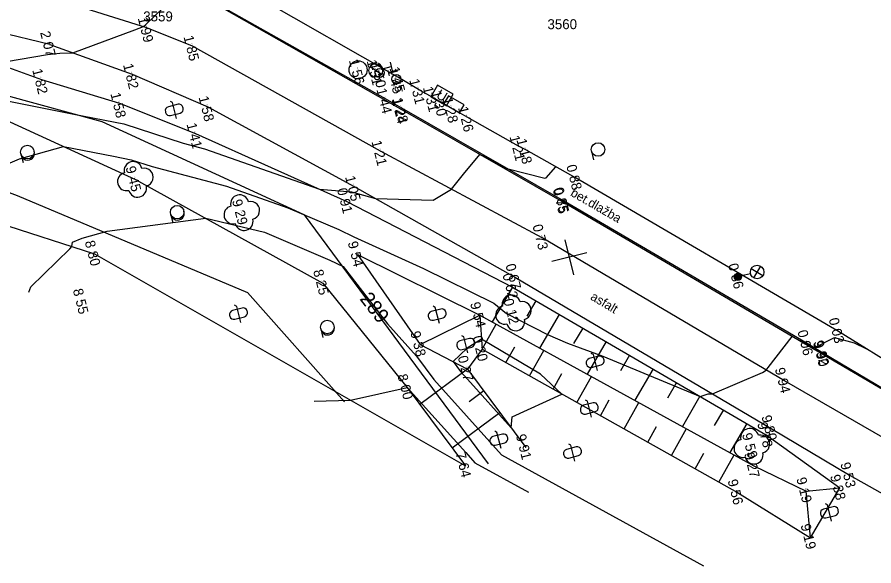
# Model space of a CAD drawing. Extents: x -740053 to -737517, y -1033516 to -1032488.
# Drawn here: x -739094.08 to -739046.71, y -1032604 to -1032573.66 of the extents above; entities that cross this region are included whole.
import ezdxf

# ---------------------------------------------------------------- set-up
doc = ezdxf.new("R2010")
doc.units = 0
for name, color, linetype in [('bod-cislo', 7, 'Continuous'), ('bod-oznac', 7, 'Continuous'), ('bod-vyska', 7, 'Continuous'), ('bod-vyska100', 7, 'Continuous'), ('chodnik', 7, 'Continuous'), ('Contours', 7, 'Continuous'), ('Contours highlighted', 7, 'Continuous'), ('Contours text', 7, 'Continuous'), ('ctv-sit', 7, 'Continuous'), ('el-zariz', 7, 'Continuous'), ('Hranice-zelene', 7, 'Continuous'), ('nazvy-bud-povr', 7, 'Continuous'), ('objekty-na-kanalizaci', 7, 'Continuous'), ('objekty-na-plynovodu', 7, 'Continuous'), ('objekty-na-vodovodu', 7, 'Continuous'), ('osa-komunikace', 7, 'Continuous'), ('Ploty-Vjezd', 7, 'Continuous'), ('podezdivka', 7, 'Continuous'), ('silnice', 7, 'Continuous'), ('Technické šrafy', 7, 'Continuous'), ('Terenni-hrana', 7, 'Continuous'), ('Znacky-kultury', 7, 'Continuous')]:
    doc.layers.add(name, color=color, linetype=linetype)

# ---------------------------------------------------------------- blocks, each defined once
blk = doc.blocks.new('el_lamst')
for p, q in [((-0.53, 1.658), (0.53, 2.719)), ((-0.53, 2.719), (0.53, 1.658)), ((0, 1.439), (0, 0.4))]:
    blk.add_line(p, q)
for centre, radius in [((0, 2.189), 0.75), ((0, 0), 0.4), ((0, 0), 0.351), ((0, 0), 0.305), ((0, 0), 0.305), ((0, 0), 0.26), ((0, 0), 0.206), ((0, 0), 0.161), ((0, 0), 0.115), ((0, 0), 0.0619)]:
    blk.add_circle(centre, radius)
blk = doc.blocks.new('el_rozd')
for p, q in [((-1.001, 1.001), (-1.001, 0)), ((1.001, 1.001), (-1.001, 1.001)), ((1.001, 0), (1.001, 1.001)), ((-1.001, 0), (1.001, 0))]:
    blk.add_line(p, q)
blk = doc.blocks.new('po_sasou')
for p, q in [((-1.055, 0.76), (-1.055, -0.734)), ((0.948, 0.76), (-1.055, 0.76)), ((0.948, -0.734), (0.948, 0.76)), ((-1.055, -0.734), (0.948, -0.734))]:
    blk.add_line(p, q)
blk.add_text('U', height=1.095).set_placement((-0.583, -0.534))
blk = doc.blocks.new('vo_soupe')
blk.add_circle((0, 0), 0.5)
blk = doc.blocks.new('po_hydpo')
for p, q in [((-0.5, 1.756), (0.5, 1.756)), ((0, 0.75), (0, 1.756)), ((-0.562, -0.496), (0.562, 0.496))]:
    blk.add_line(p, q)
blk.add_circle((0, 0), 0.75)
blk = doc.blocks.new('po_kansa')
blk.add_circle((0, 0), 1)
blk = doc.blocks.new('POINT_DISPLAY')
blk.add_line((0, 0), (0, 0))
blk = doc.blocks.new('p_strom')
for centre, start, end in [((0, 1), 0, 180), ((-1, 0), 90, 270), ((1, 0), 270, 90), ((0, -1), 180, 0)]:
    blk.add_arc(centre, 1, start, end)
at = {"rotation": -180}
blk.add_blockref('POINT_DISPLAY', (0, 0), dxfattribs=at)
blk = doc.blocks.new('p_leskro')
blk.add_line((0, -0.75), (1.001, -0.75))
blk.add_circle((0, 0), 0.75)
blk.add_arc((0.134, 0), 0.75, 264.88323, 95.11677)
blk = doc.blocks.new('p_neplod')
for p, q in [((0.052, 1.005), (-0.044, 1.005)), ((-0.824, 0.004), (-0.994, -0.184)), ((1.002, 0.004), (-0.824, 0.004)), ((-0.494, 0.555), (-0.494, -0.548)), ((0.502, -0.548), (0.502, 0.555)), ((-0.044, -0.998), (0.052, -0.998))]:
    blk.add_line(p, q)
for centre, start, end in [((-0.044, 0.555), 90, 180), ((0.052, 0.555), 0, 90), ((-0.044, -0.548), 180, 270), ((0.052, -0.548), 270, 0)]:
    blk.add_arc(centre, 0.45, start, end)
blk = doc.blocks.new('p_zahr')
blk.add_line((0, -0.75), (0.993, -0.75))
blk.add_circle((0, 0), 0.75)
blk = doc.blocks.new('ctvsit')
for p, q in [((0, -2), (0, 2)), ((2, 0), (-2, 0))]:
    blk.add_line(p, q)

msp = doc.modelspace()

# ---------------------------------------------------------------- linework, layer by layer
at = {"layer": 'chodnik'}
for p, q in [((-739073.709, -1032578.179), (-739083.274, -1032572.791)), ((-739072.816, -1032578.697), (-739073.709, -1032578.179)), ((-739063.875, -1032583.819), (-739072.816, -1032578.697)), ((-739063.171, -1032582.559), (-739065.956, -1032581.002)), ((-739050.391, -1032591.706), (-739063.875, -1032583.819)), ((-739049.498, -1032592.265), (-739050.391, -1032591.706)), ((-739042.865, -1032596.205), (-739049.498, -1032592.265))]:
    msp.add_line(p, q, dxfattribs=at)
at = {"layer": 'Contours'}
for points in [[(-739113.301, -1032585.141), (-739112.468, -1032582.989), (-739111.701, -1032582.242), (-739110.056, -1032580.212), (-739109.326, -1032576.302), (-739107.888, -1032575.694), (-739099.85, -1032575.084), (-739095.564, -1032576.081), (-739094.668, -1032576.103), (-739092.396, -1032575.717), (-739091.714, -1032575.641), (-739090.99, -1032575.637), (-739087.57, -1032574.358), (-739087.088, -1032574.182), (-739086.97, -1032574.064), (-739086.008, -1032573.134), (-739085.07, -1032572.23), (-739084.95, -1032572.102), (-739084.144, -1032572.423), (-739083.274, -1032572.791), (-739082.501, -1032571.634), (-739082.49, -1032571.595), (-739082.473, -1032571.58)], [(-739106.678, -1032586.38), (-739106.087, -1032584.852), (-739104.854, -1032583.652), (-739103.724, -1032582.257), (-739103.221, -1032579.569), (-739099.261, -1032577.893), (-739097.133, -1032577.731), (-739095.113, -1032578.202), (-739090.94, -1032579.015), (-739088.178, -1032579.564), (-739084.905, -1032580.63), (-739083.714, -1032580.945), (-739077.353, -1032583.178), (-739075.586, -1032583.317), (-739074.268, -1032583.681), (-739071.085, -1032583.783), (-739070.071, -1032583.165), (-739069.392, -1032582.342), (-739068.487, -1032581.25), (-739068.119, -1032581.426), (-739066.994, -1032582.032), (-739064.906, -1032582.558), (-739064.821, -1032582.539), (-739064.285, -1032581.936)], [(-739093.433, -1032588.859), (-739093.324, -1032588.578), (-739091.162, -1032586.473), (-739091.059, -1032586.346), (-739091.013, -1032586.102), (-739090.484, -1032585.878), (-739089.1, -1032585.486), (-739083.651, -1032584.78), (-739080.403, -1032585.555), (-739076.796, -1032587.091), (-739076.056, -1032587.446), (-739073.604, -1032590.613), (-739071.993, -1032592.41), (-739071.038, -1032593.692), (-739069.231, -1032595.703), (-739067.296, -1032597.857), (-739056.121, -1032604.001)], [(-739077.664, -1032594.886), (-739075.655, -1032594.831), (-739072.507, -1032594.139), (-739069.277, -1032597.734), (-739068.765, -1032598.304), (-739065.807, -1032599.931)]]:
    msp.add_lwpolyline(points, dxfattribs=at)
at = {"layer": 'Contours highlighted'}
for points in [[(-739097.117, -1032582.835), (-739093.942, -1032581.492), (-739091.522, -1032580.807), (-739088.747, -1032581.348), (-739087.767, -1032581.543), (-739086.606, -1032581.921), (-739082.509, -1032583.006), (-739079.11, -1032584.199), (-739076.3, -1032585.396), (-739075.454, -1032585.802), (-739071.61, -1032587.552), (-739067.726, -1032589.481), (-739067.02, -1032590.039), (-739064.76, -1032591.204), (-739063.653, -1032591.681), (-739061.69, -1032592.401), (-739056.306, -1032594.636), (-739055.876, -1032594.497), (-739055.637, -1032594.486), (-739052.868, -1032593.305), (-739052.662, -1032593.174), (-739052.554, -1032593.04), (-739051.232, -1032591.313), (-739050.072, -1032591.931), (-739050.009, -1032591.946), (-739048.891, -1032591.37), (-739047.791, -1032591.659), (-739047.111, -1032592.004)], [(-739066.707, -1032595.767), (-739063.958, -1032594.501), (-739065.136, -1032593.408), (-739068.405, -1032591.456), (-739069.204, -1032591.958), (-739069.97, -1032592.708), (-739069.57, -1032593.245), (-739069.186, -1032593.673), (-739066.763, -1032596.369), (-739066.707, -1032595.767)]]:
    msp.add_lwpolyline(points, dxfattribs=at)
at = {"layer": 'Hranice-zelene'}
for points in [[(-739078.209, -1032584.588), (-739089.378, -1032579.455), (-739100.31, -1032576.455), (-739110.269, -1032573.521), (-739112.226, -1032576.709), (-739094.074, -1032583.522), (-739081.338, -1032588.881), (-739075.972, -1032594.939)], [(-739078.209, -1032584.588), (-739068.034, -1032598.36)]]:
    msp.add_lwpolyline(points, dxfattribs=at)
at = {"layer": 'osa-komunikace'}
for p, q in [((-739086.9, -1032574.24), (-739091.787, -1032572.728)), ((-739084.373, -1032575.265), (-739086.9, -1032574.24)), ((-739073.983, -1032581.064), (-739084.373, -1032575.265)), ((-739065.041, -1032585.866), (-739073.983, -1032581.064)), ((-739051.644, -1032593.775), (-739065.041, -1032585.866)), ((-739044.094, -1032598.123), (-739051.644, -1032593.775))]:
    msp.add_line(p, q, dxfattribs=at)
at = {"layer": 'Ploty-Vjezd'}
for p, q in [((-739071.136, -1032578.078), (-739071.891, -1032577.66)), ((-739066.349, -1032580.792), (-739069.196, -1032579.188))]:
    msp.add_line(p, q, dxfattribs=at)
msp.add_lwpolyline([(-739044.07, -1032593.837), (-739045.041, -1032593.298), (-739048.663, -1032591.034)], dxfattribs=at)
at = {"layer": 'podezdivka'}
for p, q in [((-739072.986, -1032576.997), (-739083.163, -1032571.186)), ((-739071.891, -1032577.66), (-739072.986, -1032576.997)), ((-739069.196, -1032579.188), (-739071.136, -1032578.078)), ((-739065.956, -1032581.002), (-739066.349, -1032580.792)), ((-739048.663, -1032591.034), (-739063.171, -1032582.559))]:
    msp.add_line(p, q, dxfattribs=at)
at = {"layer": 'silnice'}
for p, q in [((-739072.867, -1032578.741), (-739083.293, -1032572.838)), ((-739092.263, -1032575.178), (-739100.244, -1032573.217)), ((-739092.263, -1032575.178), (-739087.716, -1032576.817)), ((-739087.716, -1032576.817), (-739083.541, -1032578.613)), ((-739083.541, -1032578.613), (-739075.44, -1032583.018)), ((-739063.926, -1032583.863), (-739072.867, -1032578.741)), ((-739075.44, -1032583.018), (-739066.531, -1032588.056)), ((-739049.539, -1032592.306), (-739063.926, -1032583.863)), ((-739066.531, -1032588.056), (-739052.385, -1032596.405)), ((-739042.882, -1032596.22), (-739049.539, -1032592.306)), ((-739052.385, -1032596.405), (-739048.027, -1032599.01)), ((-739048.027, -1032599.01), (-739045.626, -1032600.354))]:
    msp.add_line(p, q, dxfattribs=at)
at = {"layer": 'Technické šrafy'}
for p, q in [((-739066.697, -1032588.582), (-739067.822, -1032590.513)), ((-739065.401, -1032589.337), (-739065.905, -1032590.202)), ((-739064.105, -1032590.093), (-739065.192, -1032591.957)), ((-739068.368, -1032592.024), (-739067.591, -1032590.641)), ((-739062.809, -1032590.848), (-739063.312, -1032591.712)), ((-739061.513, -1032591.603), (-739062.561, -1032593.401)), ((-739067.06, -1032592.759), (-739066.57, -1032591.887)), ((-739065.752, -1032593.493), (-739064.961, -1032592.084)), ((-739060.217, -1032592.358), (-739060.72, -1032593.222)), ((-739069.174, -1032593.124), (-739071.807, -1032595.08)), ((-739058.921, -1032593.113), (-739059.93, -1032594.845)), ((-739064.444, -1032594.228), (-739063.954, -1032593.356)), ((-739063.136, -1032594.962), (-739062.331, -1032593.528)), ((-739057.625, -1032593.868), (-739058.128, -1032594.732)), ((-739068.279, -1032594.328), (-739069.082, -1032594.925)), ((-739056.329, -1032594.623), (-739057.299, -1032596.289)), ((-739061.828, -1032595.697), (-739061.339, -1032594.825)), ((-739060.52, -1032596.431), (-739059.7, -1032594.971)), ((-739067.385, -1032595.533), (-739070.018, -1032597.489)), ((-739055.032, -1032595.378), (-739055.536, -1032596.242)), ((-739059.213, -1032597.166), (-739058.723, -1032596.294)), ((-739057.905, -1032597.9), (-739057.07, -1032596.414)), ((-739053.736, -1032596.133), (-739054.668, -1032597.733)), ((-739056.597, -1032598.635), (-739056.107, -1032597.763)), ((-739055.289, -1032599.369), (-739054.44, -1032597.858))]:
    msp.add_line(p, q, dxfattribs=at)
at = {"layer": 'Terenni-hrana'}
for p, q in [((-739100.746, -1032574.21), (-739092.738, -1032577.102)), ((-739122.848, -1032576.082), (-739089.792, -1032586.755)), ((-739092.738, -1032577.102), (-739088.416, -1032578.417)), ((-739088.416, -1032578.417), (-739084.208, -1032580.101)), ((-739096.155, -1032578.684), (-739087.541, -1032582.631)), ((-739084.208, -1032580.101), (-739075.849, -1032583.853)), ((-739087.541, -1032582.631), (-739077.168, -1032588.362)), ((-739075.849, -1032583.853), (-739066.697, -1032588.582)), ((-739089.792, -1032586.755), (-739069.293, -1032598.465)), ((-739075.255, -1032586.787), (-739068.49, -1032590.147)), ((-739075.255, -1032586.787), (-739071.798, -1032591.753)), ((-739077.168, -1032588.362), (-739072.507, -1032594.139)), ((-739066.697, -1032588.582), (-739052.619, -1032596.784)), ((-739071.798, -1032591.753), (-739068.49, -1032590.147)), ((-739068.49, -1032590.147), (-739053.342, -1032598.461)), ((-739068.49, -1032590.147), (-739068.368, -1032592.024)), ((-739071.798, -1032591.753), (-739069.174, -1032593.124)), ((-739068.368, -1032592.024), (-739069.174, -1032593.124)), ((-739068.368, -1032592.024), (-739054.256, -1032599.949)), ((-739069.174, -1032593.124), (-739065.96, -1032597.451)), ((-739072.507, -1032594.139), (-739069.293, -1032598.465)), ((-739052.619, -1032596.784), (-739048.588, -1032599.688)), ((-739053.342, -1032598.461), (-739050.448, -1032599.877)), ((-739050.448, -1032599.877), (-739048.588, -1032599.688)), ((-739050.214, -1032602.448), (-739050.448, -1032599.877)), ((-739054.256, -1032599.949), (-739050.214, -1032602.448))]:
    msp.add_line(p, q, dxfattribs=at)
msp.add_lwpolyline([(-739050.214, -1032602.448), (-739048.588, -1032599.688)], dxfattribs=at)

# ---------------------------------------------------------------- block references
at = {"layer": 'bod-oznac', "rotation": -75.86979040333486}
for p in [(-739086.9, -1032574.24), (-739092.263, -1032575.178), (-739084.373, -1032575.265), (-739075.228, -1032576.571), (-739074.25, -1032576.604), (-739092.738, -1032577.102), (-739087.716, -1032576.817), (-739074.029, -1032576.744), (-739073.11, -1032577.08), (-739072.986, -1032576.997), (-739071.891, -1032577.66), (-739071.136, -1032578.078), (-739088.416, -1032578.417), (-739073.709, -1032578.179), (-739070.685, -1032578.315), (-739083.541, -1032578.613), (-739072.867, -1032578.741), (-739072.816, -1032578.697), (-739070.053, -1032578.692), (-739069.196, -1032579.188), (-739084.208, -1032580.101), (-739066.349, -1032580.792), (-739073.983, -1032581.064), (-739065.956, -1032581.002), (-739087.541, -1032582.631), (-739063.171, -1032582.559), (-739075.44, -1032583.018), (-739075.849, -1032583.853), (-739063.926, -1032583.863), (-739063.875, -1032583.819), (-739081.654, -1032584.469), (-739065.041, -1032585.866), (-739089.792, -1032586.755), (-739075.255, -1032586.787), (-739066.531, -1032588.056), (-739054.227, -1032588.021), (-739077.168, -1032588.362), (-739066.697, -1032588.582), (-739090.452, -1032589.417), (-739068.49, -1032590.147), (-739066.637, -1032590.011), (-739048.663, -1032591.034), (-739071.798, -1032591.753), (-739050.391, -1032591.706), (-739068.368, -1032592.024), (-739049.539, -1032592.306), (-739049.498, -1032592.265), (-739069.174, -1032593.124), (-739072.507, -1032594.139), (-739051.644, -1032593.775), (-739052.385, -1032596.405), (-739052.619, -1032596.784), (-739065.96, -1032597.451), (-739053.458, -1032597.387), (-739069.293, -1032598.465), (-739053.342, -1032598.461), (-739048.027, -1032599.01), (-739050.448, -1032599.877), (-739048.588, -1032599.688), (-739054.256, -1032599.949), (-739050.214, -1032602.448)]:
    msp.add_blockref('POINT_DISPLAY', p, dxfattribs=at)
at = {"layer": 'ctv-sit', "xscale": 0.49999999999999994, "yscale": 0.5, "rotation": 104.13020959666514}
msp.add_blockref('ctvsit', (-739063.554, -1032586.935), dxfattribs=at)
at = {"layer": 'el-zariz'}
for name, p, xscale, yscale, rotation in [('el_rozd', (-739070.053, -1032578.692), 0.4999999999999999, 0.49999999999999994, -30.051334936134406), ('el_lamst', (-739054.227, -1032588.021), 0.49999999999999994, 0.4999999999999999, -75.86979040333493)]:
    msp.add_blockref(name, p, dxfattribs=dict(at, xscale=xscale, yscale=yscale, rotation=rotation))
at = {"layer": 'objekty-na-kanalizaci', "xscale": 0.49999999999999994, "yscale": 0.4999999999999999, "rotation": -75.86979040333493}
msp.add_blockref('po_kansa', (-739075.228, -1032576.571), dxfattribs=at)
at = {"layer": 'objekty-na-plynovodu', "xscale": 0.49999999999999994, "yscale": 0.49999999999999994, "rotation": -30.400163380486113}
msp.add_blockref('po_sasou', (-739070.569, -1032578.013), dxfattribs=at)
at = {"layer": 'objekty-na-vodovodu', "xscale": 0.49999999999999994, "yscale": 0.4999999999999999, "rotation": -75.86979040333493}
for name, p in [('po_hydpo', (-739074.25, -1032576.604)), ('vo_soupe', (-739074.029, -1032576.744)), ('vo_soupe', (-739073.11, -1032577.08))]:
    msp.add_blockref(name, p, dxfattribs=at)
at = {"layer": 'Znacky-kultury', "xscale": 0.49999999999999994}
for name, p, yscale, rotation in [('p_neplod', (-739085.391, -1032578.784), 0.5, -75.86979040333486), ('p_leskro', (-739093.509, -1032581.121), 0.5, -75.86979040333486), ('p_zahr', (-739061.96, -1032580.979), 0.5, -75.86979040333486), ('p_strom', (-739087.541, -1032582.631), 0.4999999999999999, -75.86979040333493), ('p_strom', (-739081.654, -1032584.469), 0.4999999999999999, -75.86979040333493), ('p_leskro', (-739085.228, -1032584.442), 0.5, -75.86979040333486), ('p_strom', (-739066.637, -1032590.011), 0.4999999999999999, -75.86979040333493), ('p_neplod', (-739081.841, -1032590.052), 0.5, -75.86979040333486), ('p_neplod', (-739070.859, -1032590.108), 0.5, -75.86979040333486), ('p_leskro', (-739076.929, -1032590.794), 0.5, -75.86979040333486), ('p_neplod', (-739069.276, -1032591.733), 0.5, -75.86979040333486), ('p_neplod', (-739062.121, -1032592.716), 0.5, -75.86979040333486), ('p_neplod', (-739062.446, -1032595.294), 0.5, -75.86979040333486), ('p_neplod', (-739067.449, -1032597.021), 0.5, -75.86979040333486), ('p_strom', (-739053.458, -1032597.387), 0.4999999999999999, -75.86979040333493), ('p_neplod', (-739063.373, -1032597.73), 0.5, -75.86979040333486), ('p_neplod', (-739049.17, -1032601.035), 0.5, -75.86979040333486)]:
    msp.add_blockref(name, p, dxfattribs=dict(at, yscale=yscale, rotation=rotation))

# ---------------------------------------------------------------- texts
at = {"layer": 'bod-cislo'}
for s, p in [('3559', (-739087.105, -1032573.893)), ('3560', (-739064.758, -1032574.323))]:
    msp.add_text(s, height=0.55, dxfattribs=at).set_placement(p)
at = {"layer": 'bod-vyska'}
for s, p in [('1 99', (-739087.41, -1032573.717)), ('2 07', (-739092.811, -1032574.503)), ('1 85', (-739084.883, -1032574.741)), ('1 56', (-739075.738, -1032576.048)), ('1 51', (-739074.76, -1032576.081)), ('1 50', (-739074.539, -1032576.221)), ('1 82', (-739093.248, -1032576.579)), ('1 82', (-739088.225, -1032576.294)), ('1 45', (-739073.619, -1032576.557)), ('1 45', (-739073.496, -1032576.474)), ('1 31', (-739072.401, -1032577.137)), ('1 44', (-739074.219, -1032577.656)), ('1 31', (-739071.646, -1032577.555)), ('1 58', (-739088.926, -1032577.894)), ('1 58', (-739084.051, -1032578.089)), ('1 30', (-739071.194, -1032577.792)), ('1 24', (-739073.377, -1032578.217)), ('1 28', (-739073.326, -1032578.174)), ('1 28', (-739070.563, -1032578.169)), ('1 26', (-739069.706, -1032578.665)), ('1 41', (-739084.718, -1032579.577)), ('1 21', (-739066.859, -1032580.268)), ('1 18', (-739066.475, -1032580.441)), ('1 21', (-739074.493, -1032580.54)), ('9 45', (-739088.086, -1032581.968)), ('0 88', (-739063.719, -1032581.884)), ('1 05', (-739075.95, -1032582.495)), ('0 91', (-739076.397, -1032583.178)), ('0 75', (-739064.474, -1032583.187)), ('0 85', (-739064.423, -1032583.144)), ('9 29', (-739082.199, -1032583.806)), ('0 73', (-739065.589, -1032585.19)), ('8 80', (-739090.34, -1032586.08)), ('9 54', (-739075.8, -1032586.124)), ('0 67', (-739067.082, -1032587.368)), ('0 36', (-739054.775, -1032587.345)), ('8 25', (-739077.716, -1032587.686)), ('0 62', (-739067.249, -1032587.894)), ('8 55', (-739091.001, -1032588.741)), ('9 54', (-739069.035, -1032589.484)), ('0 12', (-739067.195, -1032589.297)), ('0 03', (-739049.211, -1032590.358)), ('9 38', (-739072.343, -1032591.091)), ('0 20', (-739068.916, -1032591.349)), ('0 06', (-739050.94, -1032591.031)), ('9 90', (-739050.084, -1032591.643)), ('9 92', (-739050.043, -1032591.602)), ('0 27', (-739069.722, -1032592.449)), ('9 94', (-739052.189, -1032593.112)), ('8 00', (-739073.055, -1032593.463)), ('9 78', (-739053.164, -1032596.121)), ('9 80', (-739052.93, -1032595.742)), ('9 91', (-739066.505, -1032596.788)), ('9 59', (-739054.003, -1032596.724)), ('7 64', (-739069.845, -1032597.777)), ('9 27', (-739053.887, -1032597.798)), ('9 53', (-739048.572, -1032598.347)), ('9 38', (-739049.133, -1032599.025)), ('9 56', (-739054.801, -1032599.286)), ('9 19', (-739051.003, -1032599.176)), ('9 19', (-739050.768, -1032601.747))]:
    msp.add_text(s, height=0.55, rotation=284.1302, dxfattribs=at).set_placement(p)
at = {"layer": 'bod-vyska100'}
for s, p in [('291 99', (-739086.971, -1032574.094)), ('292 07', (-739092.336, -1032575.024)), ('291 85', (-739084.445, -1032575.118)), ('291 82', (-739087.787, -1032576.671)), ('291 56', (-739075.299, -1032576.425)), ('291 51', (-739074.322, -1032576.457)), ('291 50', (-739074.101, -1032576.597)), ('291 82', (-739092.809, -1032576.955)), ('291 45', (-739073.181, -1032576.933)), ('291 45', (-739073.057, -1032576.85)), ('291 31', (-739071.962, -1032577.513)), ('291 44', (-739073.781, -1032578.033)), ('291 31', (-739071.207, -1032577.931)), ('291 58', (-739088.488, -1032578.27)), ('291 58', (-739083.612, -1032578.466)), ('291 24', (-739072.938, -1032578.594)), ('291 28', (-739072.887, -1032578.55)), ('291 30', (-739070.756, -1032578.168)), ('291 28', (-739070.125, -1032578.546)), ('291 26', (-739069.268, -1032579.041)), ('291 41', (-739084.279, -1032579.954)), ('291 21', (-739074.055, -1032580.917)), ('291 21', (-739066.42, -1032580.645)), ('291 18', (-739066.028, -1032580.852)), ('289 45', (-739087.614, -1032582.478)), ('290 88', (-739063.244, -1032582.406)), ('291 05', (-739075.512, -1032582.872)), ('290 91', (-739075.922, -1032583.7)), ('290 75', (-739063.999, -1032583.709)), ('290 85', (-739063.948, -1032583.665)), ('289 29', (-739081.727, -1032584.317)), ('290 73', (-739065.114, -1032585.712)), ('288 80', (-739089.865, -1032586.601)), ('289 54', (-739075.327, -1032586.634)), ('290 67', (-739066.604, -1032587.901)), ('290 36', (-739054.3, -1032587.867)), ('288 25', (-739077.241, -1032588.208)), ('290 62', (-739066.771, -1032588.427)), ('288 55', (-739090.526, -1032589.263)), ('290 12', (-739066.711, -1032589.854)), ('289 54', (-739068.562, -1032589.995)), ('290 03', (-739048.736, -1032590.88)), ('289 38', (-739071.87, -1032591.601)), ('290 06', (-739050.465, -1032591.552)), ('290 20', (-739068.441, -1032591.871)), ('289 90', (-739049.612, -1032592.154)), ('289 92', (-739049.571, -1032592.112)), ('290 27', (-739069.247, -1032592.971)), ('289 94', (-739051.717, -1032593.622)), ('288 00', (-739072.58, -1032593.985)), ('289 80', (-739052.457, -1032596.252)), ('289 78', (-739052.692, -1032596.631)), ('289 91', (-739066.033, -1032597.298)), ('289 59', (-739053.53, -1032597.234)), ('287 64', (-739069.367, -1032598.31)), ('289 27', (-739053.415, -1032598.308)), ('289 53', (-739048.1, -1032598.857)), ('289 56', (-739054.329, -1032599.796)), ('289 19', (-739050.522, -1032599.721)), ('289 38', (-739048.661, -1032599.535)), ('289 19', (-739050.287, -1032602.292))]:
    msp.add_text(s, height=0.05, rotation=284.1302, dxfattribs=at).set_placement(p)
at = {"layer": 'Contours text'}
msp.add_text('289', height=0.8, rotation=307.7517, dxfattribs=at).set_placement((-739075.169, -1032589.245))
at = {"layer": 'nazvy-bud-povr'}
for s, rotation, p in [('bet.dlažba', 329.9957, (-739063.527, -1032583.506)), ('asfalt', 329.1142, (-739062.424, -1032589.245))]:
    msp.add_text(s, height=0.5, rotation=rotation, dxfattribs=at).set_placement(p)

doc.saveas('drawing.dxf')
